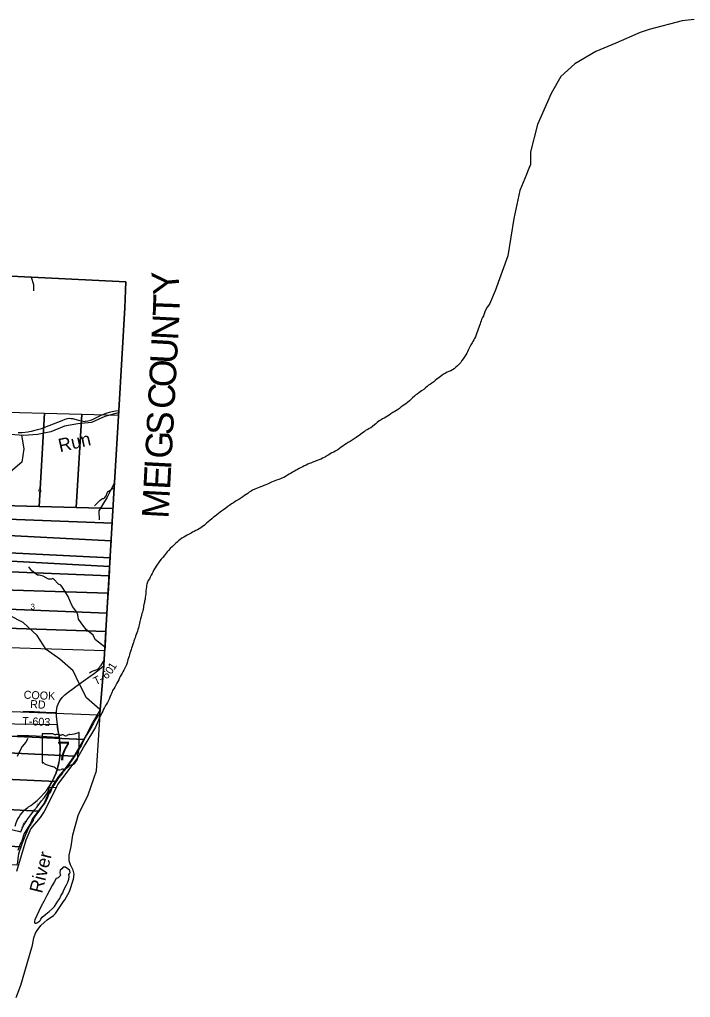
# Model space of a CAD drawing. Extents: x 1878108 to 2183446, y 146837 to 508383.
# Drawn here: x 2079424 to 2104590, y 338670 to 375322 of the extents above; entities that cross this region are included whole.
import ezdxf

# ---------------------------------------------------------------- set-up
doc = ezdxf.new("R2010")
doc.units = 0
for name, color, linetype in [('GM_X_Adjacent_County', 7, 'Continuous'), ('GM_X_Adjacent_County_Text', 7, 'Continuous'), ('GM_X_City_Street', 7, 'Continuous'), ('GM_X_City_Street_Text', 7, 'Continuous'), ('GM_X_Corporation', 7, 'Continuous'), ('GM_X_County', 7, 'Continuous'), ('GM_X_Major_River', 7, 'Continuous'), ('GM_X_Major_River_Text', 7, 'Continuous'), ('GM_X_Minor_River', 7, 'Continuous'), ('GM_X_Minor_River_Text', 7, 'Continuous'), ('GM_X_Section', 7, 'Continuous'), ('GM_X_Section_Text', 7, 'Continuous'), ('GM_X_State_Location', 7, 'Continuous'), ('GM_X_State_Route', 7, 'Continuous'), ('GM_X_State_Shield', 7, 'Continuous'), ('GM_X_Township', 7, 'Continuous'), ('GM_X_Township_Road', 7, 'Continuous'), ('GM_X_Township_Road_Text', 7, 'Continuous'), ('GM_X_Township_ROW', 7, 'Continuous')]:
    doc.layers.add(name, color=color, linetype=linetype)

msp = doc.modelspace()

# ---------------------------------------------------------------- linework, layer by layer
at = {"layer": 'GM_X_Adjacent_County'}
msp.add_lwpolyline([(2104734, 375322), (2104277, 375272), (2103045, 374949), (2102700, 374839), (2101785, 374433), (2101038, 374126), (2100258, 373658), (2099729, 373189), (2099361, 372548), (2098848, 371389), (2098592, 370359), (2098593, 369895), (2098493, 369647), (2098440, 369520), (2098190, 368920), (2097966, 367859), (2097734, 366472), (2097267, 365160), (2097048, 364648), (2096963, 364544), (2096906, 364426), (2096881, 364363), (2096854, 364288), (2096821, 364217), (2096792, 364150), (2096757, 364082), (2096740, 364031), (2096713, 363966), (2096696, 363916), (2096677, 363853), (2096654, 363782), (2096630, 363718), (2096602, 363637), (2096583, 363576), (2096556, 363504), (2096531, 363435), (2096495, 363372), (2096464, 363319), (2096425, 363252), (2096400, 363202), (2096353, 363126), (2096314, 363053), (2096289, 363003), (2096254, 362928), (2096222, 362871), (2096197, 362814), (2096164, 362750), (2096117, 362680), (2096066, 362611), (2096019, 362540), (2095974, 362471), (2095917, 362406), (2095851, 362345), (2095790, 362291), (2095731, 362236), (2095669, 362195), (2095601, 362156), (2095528, 362128), (2095460, 362103), (2095406, 362072), (2095332, 362025), (2095269, 361975), (2095209, 361938), (2095158, 361901), (2095080, 361840), (2095015, 361790), (2094958, 361741), (2094884, 361688), (2094833, 361655), (2094763, 361613), (2094709, 361570), (2094650, 361519), (2094583, 361458), (2094507, 361404), (2094454, 361369), (2094400, 361328), (2094345, 361285), (2094291, 361250), (2094235, 361205), (2094162, 361141), (2094105, 361080), (2094050, 361025), (2093982, 360974), (2093915, 360924), (2093857, 360875), (2093806, 360844), (2093732, 360791), (2093673, 360748), (2093607, 360694), (2093538, 360653), (2093482, 360624), (2093426, 360591), (2093357, 360545), (2093287, 360496), (2093230, 360459), (2093162, 360416), (2093096, 360378), (2093043, 360353), (2092987, 360320), (2092911, 360277), (2092844, 360224), (2092793, 360175), (2092737, 360127), (2092664, 360074), (2092598, 360025), (2092543, 359988), (2092491, 359959), (2092403, 359913), (2092348, 359874), (2092292, 359829), (2092215, 359769), (2092163, 359732), (2092102, 359691), (2092050, 359652), (2091973, 359605), (2091895, 359559), (2091825, 359512), (2091754, 359466), (2091672, 359417), (2091611, 359378), (2091549, 359336), (2091484, 359293), (2091420, 359244), (2091357, 359199), (2091269, 359143), (2091208, 359112), (2091134, 359076), (2091080, 359043), (2091028, 359012), (2090975, 358979), (2090905, 358938), (2090849, 358907), (2090790, 358876), (2090736, 358849), (2090682, 358826), (2090624, 358805), (2090550, 358784), (2090496, 358763), (2090425, 358733), (2090353, 358700), (2090291, 358677), (2090239, 358654), (2090173, 358625), (2090106, 358591), (2090044, 358560), (2089992, 358533), (2089911, 358492), (2089855, 358459), (2089801, 358430), (2089733, 358394), (2089666, 358355), (2089614, 358324), (2089543, 358281), (2089473, 358239), (2089403, 358194), (2089338, 358159), (2089268, 358130), (2089216, 358109), (2089144, 358083), (2089068, 358058), (2088994, 358029), (2088935, 358002), (2088879, 357979), (2088805, 357947), (2088725, 357910), (2088666, 357885), (2088590, 357857), (2088506, 357826), (2088438, 357799), (2088374, 357771), (2088316, 357748), (2088245, 357717), (2088163, 357680), (2088107, 357644), (2088042, 357605), (2087984, 357562), (2087921, 357517), (2087867, 357482), (2087799, 357436), (2087728, 357389), (2087644, 357335), (2087573, 357292), (2087513, 357255), (2087448, 357214), (2087378, 357172), (2087308, 357123), (2087235, 357068), (2087158, 357010), (2087072, 356948), (2087001, 356893), (2086947, 356854), (2086884, 356811), (2086824, 356761), (2086761, 356708), (2086701, 356671), (2086636, 356608), (2086565, 356550), (2086503, 356501), (2086434, 356440), (2086363, 356376), (2086277, 356306), (2086224, 356271), (2086158, 356232), (2086096, 356199), (2086041, 356172), (2085973, 356135), (2085915, 356104), (2085862, 356075), (2085788, 356033), (2085714, 355992), (2085647, 355959), (2085587, 355925), (2085509, 355882), (2085446, 355833), (2085392, 355786), (2085337, 355738), (2085277, 355685), (2085218, 355630), (2085163, 355577), (2085076, 355491), (2085009, 355426), (2084961, 355375), (2084926, 355324), (2084887, 355273), (2084851, 355222), (2084802, 355163), (2084737, 355096), (2084684, 355034), (2084630, 354965), (2084593, 354910), (2084554, 354839), (2084513, 354768), (2084466, 354691), (2084421, 354604), (2084394, 354554), (2084361, 354491), (2084328, 354422), (2084293, 354363), (2084254, 354296), (2084220, 354231), (2084200, 354160), (2084188, 354110), (2084181, 354056), (2084172, 353985), (2084167, 353913), (2084166, 353863), (2084161, 353800), (2084154, 353732), (2084141, 353661), (2084130, 353595), (2084115, 353520), (2084106, 353470), (2084091, 353401), (2084076, 353337), (2084069, 353284), (2084056, 353218), (2084045, 353161), (2084032, 353109), (2084016, 353056), (2083999, 352994), (2083982, 352929), (2083963, 352864), (2083946, 352806), (2083937, 352756), (2083926, 352699), (2083911, 352637), (2083901, 352584), (2083888, 352526), (2083867, 352457), (2083844, 352392), (2083825, 352340), (2083802, 352279), (2083777, 352206), (2083760, 352154), (2083738, 352095), (2083717, 352029), (2083696, 351968), (2083675, 351905), (2083652, 351829), (2083629, 351760), (2083610, 351705), (2083583, 351630), (2083566, 351574), (2083547, 351511), (2083532, 351461), (2083511, 351402), (2083488, 351329), (2083476, 351279), (2083461, 351213), (2083436, 351138), (2083399, 351063), (2083358, 350992), (2083335, 350941), (2083300, 350876), (2083267, 350822), (2083234, 350761), (2083197, 350696), (2083173, 350645), (2083142, 350580), (2083105, 350509), (2083072, 350443), (2083037, 350374), (2082998, 350305), (2082959, 350238), (2082916, 350169), (2082892, 350118), (2082871, 350066), (2082846, 350007), (2082815, 349930), (2082784, 349853), (2082763, 349803), (2082720, 349726), (2082685, 349659), (2082654, 349606), (2082615, 349541), (2082579, 349474), (2082544, 349403), (2082509, 349340), (2082424, 349144), (2082582, 351113), (2082596, 351331), (2082627, 351767), (2082976, 357786), (2082987, 357968), (2083148, 360670), (2083371, 364517), (2083412, 365486), (2078084, 365756)], dxfattribs=at)
at = {"layer": 'GM_X_City_Street'}
for points in [[(2079342, 348504), (2079568, 348493), (2079774, 348482), (2080043, 348472), (2080261, 348459), (2080647, 348439), (2080912, 348421)], [(2079471, 344882), (2079526, 344997), (2079603, 345149), (2079666, 345267), (2079730, 345361), (2079888, 345565), (2079989, 345698), (2080081, 345816), (2080170, 345933), (2080246, 346033), (2080347, 346155), (2080424, 346260), (2080478, 346333), (2080507, 346398), (2080526, 346462), (2080534, 346496), (2080535, 346521), (2080515, 346542)], [(2079049, 344988), (2079119, 344967), (2079221, 344940), (2079389, 344896), (2079471, 344882)]]:
    msp.add_lwpolyline(points, dxfattribs=at)
at = {"layer": 'GM_X_Corporation'}
msp.add_lwpolyline([(2076093, 348970), (2080828, 348900), (2080849, 348709), (2080904, 348474), (2080951, 348075), (2080939, 347719), (2080913, 347555), (2080887, 347398), (2080795, 347093), (2080675, 346817), (2080521, 346541), (2080809, 346554), (2080345, 345644), (2080199, 345413), (2079853, 344998), (2079662, 344563), (2079312, 343390)], dxfattribs=at)
at = {"layer": 'GM_X_County'}
msp.add_lwpolyline([(2078084, 365756), (2083412, 365486), (2083371, 364517), (2083148, 360670), (2082987, 357968), (2082976, 357786), (2082627, 351767), (2082596, 351331), (2082582, 351113), (2082424, 349144), (2082268, 348794), (2081870, 348134), (2081601, 347653), (2080862, 346658), (2080345, 345644), (2080199, 345413), (2079853, 344998), (2079662, 344563), (2079312, 343390)], dxfattribs=at)
at = {"layer": 'GM_X_Major_River'}
msp.add_line((2082314, 347162), (2082458, 349478), dxfattribs=at)
for points in [[(2082458, 349478), (2082128, 348897), (2081925, 348500), (2081496, 347758), (2081361, 347565), (2081137, 347254), (2080888, 346945), (2080669, 346627), (2080492, 346306), (2080342, 345950), (2080211, 345760), (2079906, 345372), (2079840, 345195), (2079593, 344814), (2079498, 344507), (2079462, 344456), (2079361, 344173)], [(2079300, 338670), (2079476, 339125), (2079627, 339645), (2079907, 340630), (2079964, 340900), (2080026, 341079), (2080085, 341183), (2080225, 341362), (2080349, 341477), (2080455, 341575), (2080698, 341746), (2080768, 341815), (2081077, 342265), (2081127, 342329), (2081296, 342646), (2081451, 343105), (2081467, 343292), (2081438, 343440), (2081338, 343644), (2081287, 343790), (2081291, 343999), (2081364, 344332), (2081417, 344763), (2081567, 345297), (2081625, 345491), (2081696, 345662), (2081985, 346228), (2082228, 346909), (2082314, 347162)], [(2079998, 341584), (2079990, 341528), (2079982, 341492), (2079999, 341456), (2080015, 341448), (2080053, 341448), (2080099, 341484), (2080166, 341532), (2080194, 341554), (2080226, 341609), (2080276, 341675), (2080414, 341796), (2080540, 341892), (2080650, 341991), (2080739, 342075), (2080797, 342184), (2080857, 342284), (2080933, 342376), (2080978, 342479), (2081042, 342591), (2081084, 342706), (2081186, 342888), (2081237, 342989), (2081269, 343097), (2081283, 343195), (2081276, 343297), (2081294, 343305), (2081322, 343350), (2081310, 343410), (2081300, 343434), (2081153, 343554)], [(2081153, 343554), (2081056, 343555), (2081004, 343495), (2080942, 343443), (2080930, 343336), (2080944, 343294), (2080954, 343270), (2080950, 343224), (2080912, 343186), (2080877, 343158), (2080829, 343138), (2080803, 343122), (2080717, 342991), (2080645, 342867), (2080556, 342702), (2080452, 342493), (2080348, 342296), (2080231, 342094), (2080145, 341909), (2079998, 341584)]]:
    msp.add_lwpolyline(points, dxfattribs=at)
at = {"layer": 'GM_X_Minor_River'}
for points in [[(2079863, 365671), (2079949, 365387), (2079943, 365154)], [(2083124, 360583), (2082620, 360439), (2082119, 360219), (2081611, 360175), (2081105, 360087), (2080593, 359867), (2080092, 359775), (2079585, 359733), (2079073, 359769), (2078556, 359880), (2078052, 359896), (2077537, 360081), (2077022, 360292), (2076581, 360801), (2076078, 360982), (2075576, 360938), (2075068, 360844), (2074568, 360801), (2074554, 360797)], [(2079503, 359739), (2079589, 359236), (2079511, 358729), (2079003, 358296), (2078499, 358056), (2077993, 358012), (2077482, 358225), (2076978, 358087), (2076644, 357585), (2076139, 357311), (2075636, 356988), (2075540, 356926)], [(2082963, 357918), (2082709, 357417), (2082400, 356911), (2082406, 356570)], [(2082616, 351813), (2082274, 352075), (2082228, 352162), (2082181, 352242), (2081921, 352456), (2081834, 352571), (2081636, 352851), (2081605, 353008), (2081575, 353115), (2081416, 353326), (2081329, 353483), (2081245, 353703), (2081038, 354037), (2080973, 354126), (2080881, 354162), (2080697, 354358), (2080675, 354366), (2080621, 354348), (2080589, 354346), (2080513, 354353), (2080311, 354454), (2080159, 354499), (2080095, 354493), (2079889, 354657), (2079774, 354808)], [(2082439, 349460), (2081938, 349901), (2081668, 350413), (2081432, 350915), (2080932, 351350), (2080428, 351715), (2080086, 352231), (2079563, 352726), (2079048, 352989), (2078762, 353503), (2078614, 354026), (2078169, 354503)], [(2079736, 348372), (2079656, 348238), (2079517, 348069), (2079444, 347935), (2079329, 347703)]]:
    msp.add_lwpolyline(points, dxfattribs=at)
at = {"layer": 'GM_X_Section'}
for points in [[(2079425, 360597), (2080358, 360572), (2080163, 357068), (2078787, 357111), (2078971, 360609)], [(2081287, 360547), (2081759, 360535), (2081543, 357034), (2080163, 357068), (2080358, 360572)], [(2082222, 360522), (2083133, 360498), (2083119, 360268), (2082929, 356999), (2081543, 357034), (2081759, 360535)], [(2078787, 357111), (2080163, 357068), (2081543, 357034), (2082929, 356999), (2082901, 356524), (2082897, 356446), (2077339, 356662), (2077368, 357156)], [(2077339, 356662), (2082897, 356446), (2082866, 355918), (2082859, 355786), (2077303, 356065)], [(2082859, 355786), (2082828, 355255), (2082821, 355142), (2077262, 355416), (2077303, 356065)], [(2077262, 355416), (2082821, 355142), (2082802, 354819), (2077244, 355123)], [(2077243, 355098), (2077244, 355123), (2082802, 354819), (2082793, 354660), (2082782, 354466), (2077216, 354703)], [(2082782, 354466), (2082755, 354011), (2082744, 353820), (2077169, 354001), (2077183, 354214), (2077216, 354703)], [(2077169, 354001), (2082744, 353820), (2082714, 353310), (2082701, 353076), (2077121, 353299)], [(2082701, 353076), (2082675, 352639), (2082660, 352382), (2077074, 352572), (2077121, 353299)], [(2077074, 352572), (2082660, 352382), (2082643, 352083), (2082618, 351655), (2077025, 351832), (2077063, 352409)], [(2076867, 349473), (2082379, 349266), (2082364, 349230), (2082335, 349176), (2082291, 349107), (2082229, 349011), (2082192, 348951), (2082156, 348889), (2082130, 348829), (2082108, 348784), (2082077, 348730), (2082039, 348668), (2081952, 348530), (2081926, 348487), (2081886, 348419), (2081848, 348335), (2076806, 348566)], [(2081848, 348335), (2081839, 348315), (2081777, 348187), (2081734, 348102), (2081690, 348030), (2081632, 347934), (2081541, 347793), (2081490, 347718), (2076764, 347950), (2076806, 348566)], [(2076764, 347950), (2081490, 347718), (2081420, 347617), (2081319, 347474), (2081181, 347286), (2081100, 347171), (2081086, 347147), (2081074, 347125), (2081064, 347109), (2081044, 347087), (2081022, 347063), (2080967, 346998), (2080891, 346900), (2080794, 346758), (2076689, 346950)], [(2076616, 345839), (2080144, 345653), (2080028, 345493), (2079958, 345391), (2079940, 345359), (2079941, 345345), (2079939, 345327), (2079937, 345313), (2079931, 345295), (2079917, 345265), (2079899, 345235), (2079875, 345195), (2079853, 345163), (2079822, 345122), (2079790, 345072), (2079754, 345010), (2079718, 344942), (2079691, 344882), (2079645, 344767), (2079570, 344577), (2079503, 344391), (2079497, 344375), (2079476, 344318), (2076512, 344479)], [(2076512, 344479), (2079476, 344318), (2079466, 344288), (2079436, 344206), (2079414, 344128), (2079389, 344034), (2079369, 343960), (2079354, 343872), (2079342, 343740), (2079336, 343682), (2079325, 343622), (2076462, 343775)]]:
    msp.add_lwpolyline(points, close=True, dxfattribs=at)
msp.add_lwpolyline([(2076689, 346950), (2080794, 346758), (2080730, 346667), (2080705, 346625), (2080675, 346577), (2080651, 346527), (2080623, 346471), (2080607, 346432), (2080594, 346402), (2080570, 346362), (2080548, 346328), (2080530, 346304), (2080514, 346272), (2080485, 346198), (2080467, 346154), (2080445, 346104), (2080425, 346056), (2080411, 346021), (2080392, 345989), (2080374, 345963), (2080346, 345927), (2080304, 345871), (2080252, 345801), (2080144, 345653), (2076616, 345839)], dxfattribs=at)
at = {"layer": 'GM_X_State_Route'}
for points in [[(2080818, 349127), (2080809, 349186), (2080805, 349251), (2080806, 349345), (2080805, 349377), (2080810, 349415), (2080824, 349493), (2080840, 349571), (2080873, 349661), (2080913, 349750), (2080960, 349829), (2081023, 349909), (2081072, 349966), (2081122, 350013), (2081196, 350077), (2081487, 350286), (2081814, 350522), (2082233, 350823), (2082415, 350963), (2082501, 351039), (2082582, 351113)], [(2080643, 346759), (2080675, 346817), (2080738, 346953), (2080795, 347093), (2080797, 347098), (2080820, 347173), (2080851, 347262), (2080887, 347398), (2080917, 347560), (2080939, 347713), (2080939, 347719), (2080949, 347895), (2080947, 348058), (2080939, 348198), (2080936, 348229), (2080927, 348320), (2080912, 348421), (2080904, 348474), (2080874, 348718), (2080847, 348900), (2080823, 349091), (2080818, 349127)], [(2079765, 345810), (2079845, 345867), (2079971, 345959), (2080083, 346052), (2080212, 346173), (2080351, 346324), (2080442, 346437), (2080515, 346542), (2080616, 346709), (2080643, 346759)], [(2079264, 345092), (2079301, 345217), (2079347, 345334), (2079392, 345420), (2079449, 345507), (2079521, 345594), (2079579, 345658), (2079640, 345713)], [(2079640, 345713), (2079650, 345721), (2079732, 345786), (2079765, 345810)]]:
    msp.add_lwpolyline(points, dxfattribs=at)
at = {"layer": 'GM_X_State_Shield'}
for p, q in [((2081661, 348029), (2081661, 348581)), ((2080269, 348537), (2080269, 347480)), ((2080690, 348555), (2080282, 348555)), ((2081661, 348029), (2081661, 348029))]:
    msp.add_line(p, q, dxfattribs=at)
for centre, radius, start, end in [((2081165, 349996), 1476, 275.8445, 288.9065), ((2081645, 348584), 15.5, 351.8621, 97.738), ((2080284, 348539), 16.1, 98.1301, 188.1301), ((2080787, 348678), 156, 231.6195, 271.1119), ((2080839, 347962), 562, 80.4867, 94.9883), ((2080966, 348545), 45.1, 219.7921, 297.1024), ((2081033, 348423), 93.8, 54.4667, 119.1411), ((2081154, 348590), 113, 233.8562, 294.8282), ((2081353, 348233), 297, 97.3462, 120.7689), ((2081716, 347797), 105, 136.8065, 186.9296), ((2081657, 347988), 24, 107.944, 210.337), ((2081504, 347918), 144, 340.033, 23.6496), ((2081644, 348027), 16.6, 289.6038, 7.7341), ((2080285, 347478), 16.3, 171.9584, 258.3066), ((2080287, 347586), 124, 267.339, 280.6039), ((2080312, 347419), 44.8, 29.7484, 93.2717), ((2081247, 347727), 369, 292.3089, 8.9858), ((2080878, 348369), 1066, 240.4129, 257.1985), ((2080560, 347006), 334, 47.1842, 75.836), ((2080921, 347414), 212, 230.7004, 286.2918), ((2081043, 347049), 174, 85.6951, 111.2099), ((2081058, 347335), 113, 268.777, 315.5493), ((2081160, 347233), 31.8, 65.7517, 132.6484), ((2081147, 347378), 119, 282.8732, 323.2771), ((2081403, 347184), 202, 94.4031, 142.5768)]:
    msp.add_arc(centre, radius, start, end, dxfattribs=at)
at = {"layer": 'GM_X_Township'}
msp.add_lwpolyline([(2078084, 365756), (2083412, 365486), (2083371, 364517), (2083148, 360670), (2082987, 357968), (2082976, 357786), (2082627, 351767), (2082596, 351331), (2082582, 351113), (2082424, 349144), (2082268, 348794), (2081870, 348134), (2081601, 347653), (2080862, 346658), (2080345, 345644), (2080199, 345413), (2079853, 344998), (2079662, 344563), (2079312, 343390)], dxfattribs=at)
at = {"layer": 'GM_X_Township_Road'}
for points in [[(2079371, 359844), (2079442, 359839), (2079516, 359842), (2079729, 359872), (2079802, 359881), (2079873, 359898), (2080012, 359932), (2080099, 359956), (2080244, 359994), (2080371, 360042), (2080536, 360107), (2080692, 360165), (2080858, 360235), (2081017, 360297), (2081140, 360346), (2081225, 360370), (2081303, 360378), (2081361, 360375), (2081422, 360367), (2081500, 360350), (2081629, 360311), (2081737, 360279), (2081804, 360263), (2081860, 360258), (2081896, 360263), (2081981, 360280), (2082092, 360311), (2082187, 360346), (2082483, 360490), (2082676, 360571), (2082792, 360612), (2082896, 360633), (2083022, 360656), (2083148, 360670)], [(2082705, 357571), (2082718, 357595), (2082744, 357630), (2082768, 357646), (2082825, 357687), (2082933, 357761), (2082975, 357780)], [(2082579, 357368), (2082589, 357368), (2082621, 357406), (2082670, 357473), (2082690, 357506), (2082692, 357531), (2082699, 357558), (2082705, 357571)], [(2082054, 350835), (2082129, 350886), (2082187, 350916), (2082258, 350937), (2082330, 350965), (2082376, 350991), (2082409, 351029), (2082439, 351077), (2082483, 351124), (2082592, 351303)], [(2079546, 349401), (2079835, 349387), (2079974, 349381), (2080405, 349362), (2080764, 349348), (2080806, 349345)]]:
    msp.add_lwpolyline(points, dxfattribs=at)
at = {"layer": 'GM_X_Township_ROW'}
msp.add_lwpolyline([(2082238, 357099), (2082370, 357229), (2082441, 357291), (2082503, 357350), (2082535, 357369), (2082557, 357368), (2082579, 357368)], dxfattribs=at)

# ---------------------------------------------------------------- texts
at = {"layer": 'GM_X_Adjacent_County_Text'}
for s, rotation, p in [('Y', 95.0933, (2085441, 365071)), ('T', 87.9416, (2085418, 364187)), ('N', 86.9342, (2085370, 363285)), ('U', 86.909, (2085322, 362401)), ('O', 86.9081, (2085274, 361518)), ('C', 86.909, (2085230, 360705)), ('S', 86.9073, (2085177, 359725)), ('G', 86.909, (2085130, 358842)), ('E', 86.9086, (2085067, 357687)), ('I', 86.908, (2085108, 358434)), ('M', 86.9085, (2085009, 356601))]:
    msp.add_text(s, height=1000, rotation=rotation, dxfattribs=at).set_placement(p)
at = {"layer": 'GM_X_City_Street_Text'}
for s, rotation, p in [('DR', 53.7481, (2080082, 345833)), ('E', 60.9671, (2079640, 345237)), ('R', 64.6296, (2079514, 344986)), ('I', 64.6334, (2079531, 345022)), ('V', 64.644, (2079540, 345042)), ('E', 64.6447, (2079559, 345082)), ('R', 64.2277, (2079574, 345113)), ('S', 62.0175, (2079591, 345149)), ('I', 61.0685, (2079607, 345180)), ('D', 60.922, (2079618, 345199))]:
    msp.add_text(s, height=50, rotation=rotation, dxfattribs=at).set_placement(p)
at = {"layer": 'GM_X_Major_River_Text'}
msp.add_text('River', height=499.8, rotation=75.9918, dxfattribs=at).set_placement((2080269, 342548))
at = {"layer": 'GM_X_Minor_River_Text'}
msp.add_text('Run', height=500, rotation=13.0015, dxfattribs=at).set_placement((2080941, 359102))
at = {"layer": 'GM_X_Section_Text'}
for s, p in [('4', (2080105, 357586)), ('3', (2079839, 353206))]:
    msp.add_text(s, height=221, rotation=0, dxfattribs=at).set_placement(p)
at = {"layer": 'GM_X_State_Location'}
msp.add_text('7', height=1, rotation=0, dxfattribs=at).set_placement((2080798, 347866))
for s in ['s', 'r']:
    msp.add_text(s, height=1, dxfattribs=at).set_placement((2080949, 347939))
at = {"layer": 'GM_X_State_Shield'}
msp.add_text('7', height=696, dxfattribs=at).set_placement((2080814, 347555))
at = {"layer": 'GM_X_Township_Road_Text'}
for s, rotation, p in [('1', 57.9592, (2082968, 350918)), ('6', 42.8321, (2082675, 350573)), ('0', 56.2536, (2082860, 350757)), ('T', 25.137, (2082277, 350367)), ('-', 26.0921, (2082485, 350465)), ('COOK', 357.3306, (2079574, 349870)), ('RD', 357.0362, (2079815, 349519)), ('T-603', 357.4735, (2079522, 348884))]:
    msp.add_text(s, height=300, rotation=rotation, dxfattribs=at).set_placement(p)

doc.saveas('drawing.dxf')
